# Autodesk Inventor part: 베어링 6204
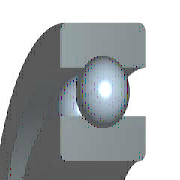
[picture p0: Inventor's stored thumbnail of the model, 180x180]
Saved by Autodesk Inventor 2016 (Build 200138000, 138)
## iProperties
Created: 2012-02
Part Number: 베어링 6204
Material: 강철, 연강
Description: 깊은 그루브 볼 베어링
Document SubType Name: Modeling
Standard: KS B 2023
Designer: mduedu
Standards Organization: KS
Language: ko-KR
Size Designation: 6203 - 17 x 40 x 12
Categories: <MemberInstance><Categories><Category DisplayName="샤프트 부품" InternalName="7f7aeb1f-a693-4053-b835-cee3144e0d98" Mnemonic="SHFT"><Category DisplayName="베어링" Inter
Density: 1 g/cm^3
Appearance: 노란색
IsCustomPart: 1
Author: mduedu
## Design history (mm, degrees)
sketch "스케치" dims "d0" = 7.02 (= -0.26 x WD + 0.26 x BD)
  geometry: L1 (3.49, 16.75)-(10.51, 16.75); L2 (7, 16.75)-(7, 13.24); L3 (7, 16.75)-(7, 20.26); L4 (4.392, 14.401)-(0, 14.401); L5 (0, 10)-(14, 10); L6 (4.392, 19.099)-(0, 19.099); L7 (0, 23.5)-(14, 23.5); L8 (14, 10)-(14, 14.401); L9 (9.608, 14.401)-(14, 14.401); L10 (9.608, 19.099)-(14, 19.099); L11 (14, 23.5)-(14, 19.099); L12 (-2.4, 0)-(14.4, 0) reference; L13 (0, 7.3)-(0, 26.2) reference
  constraints: 22 end point, 4 point on line, 2 collinear, 2 perpendicular, 2 symmetric about line, 1 midpoint, 1 parallel, 14 other
  dimensions: "d9" = 20 diameter of L5 L12 (= WD); "d11" = 47 diameter of L7 L12 (= BD); "d12" = 14 distance between parallel lines of L8 L13 (= KB); "d13" = 28.802 diameter of L9 L12 (= 0.326 x BD + 0.674 x WD)
revolve "본체" stored, may be unused: angle "d6" = 90 deg
revolve "볼" stored, may be unused: angle "d7" = 90 deg
pattern_circular "IDS_ARRAYBALL[SIMPL:T]" dims angle "d3" = 360 deg
body "Solid1"
fillet "모깎기1" dims "d1" = 1 (= KRS)
other parameters: "WD" = 20 [user parameter; used in 5 equation terms], "BD" = 47 [user parameter; used in 5 equation terms], "KB" = 14 [user parameter; used in 1 equation term], "KRS" = 1 [user parameter; used in 1 equation term], "d4" = 0, "d5" = 0, "d8" = 0, "d14" = 0, "d15" = 0, "BBA" = 0 [user parameter], "BC0" = 4750000 [user parameter], "BC" = 9560000 [user parameter], "BR" = 23.5 (= 0.5 x BD) [user parameter]
